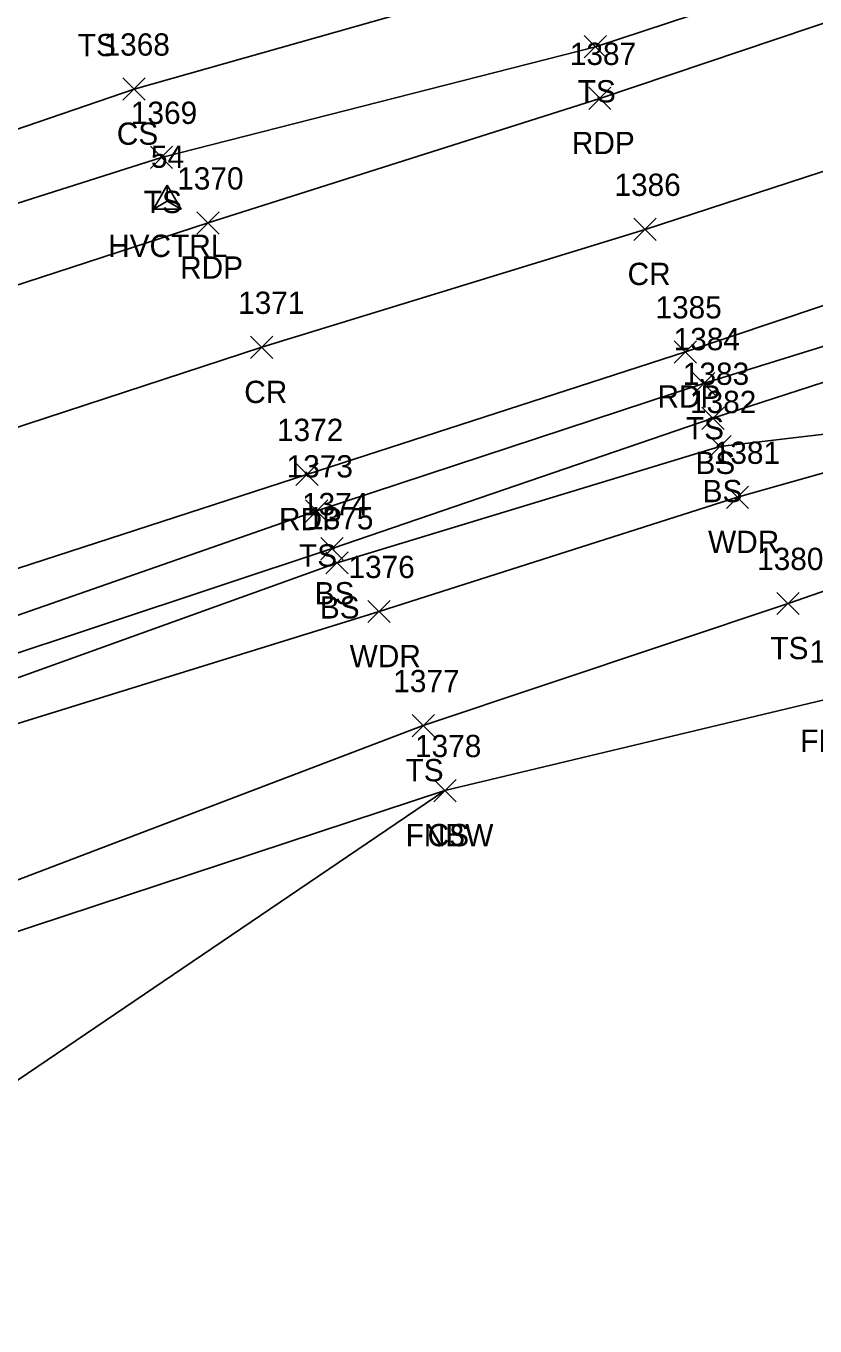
# Model space of a CAD drawing. Extents: x 1443064 to 1445163, y 544063 to 544655.
# Drawn here: x 1443595.4 to 1443666.1, y 544191.5 to 544308.2 of the extents above; entities that cross this region are included whole.
import ezdxf

# ---------------------------------------------------------------- set-up
doc = ezdxf.new("R2010")
doc.units = 0
for name, color, linetype in [('C_A', 7, 'Continuous'), ('C_I', 7, 'Continuous'), ('CPSM', 7, 'Continuous'), ('L_A', 7, 'Continuous'), ('L_I', 7, 'Continuous'), ('L_TIC', 7, 'Continuous'), ('LAWA', 7, 'Continuous'), ('LELB', 7, 'Continuous'), ('LFNC', 7, 'Continuous'), ('P_A', 7, 'Continuous'), ('P_I', 7, 'Continuous'), ('P_TIC', 7, 'Continuous'), ('PET', 7, 'Continuous'), ('PRC', 7, 'Continuous')]:
    doc.layers.add(name, color=color, linetype=linetype)

msp = doc.modelspace()

# ---------------------------------------------------------------- linework, layer by layer
at = {"layer": 'CPSM'}
for p, q in [((1443606.79, 544291.73), (1443608.04, 544293.9)), ((1443609.29, 544291.73), (1443608.04, 544293.9)), ((1443608.04, 544292.45), (1443608.04, 544293.9)), ((1443606.79, 544291.73), (1443608.04, 544292.45)), ((1443608.04, 544292.45), (1443608.04, 544292.45)), ((1443608.04, 544292.45), (1443609.29, 544291.73)), ((1443606.79, 544291.73), (1443609.29, 544291.73))]:
    msp.add_line(p, q, dxfattribs=at)
at = {"layer": 'L_TIC'}
for points in [[(1443645.45, 544305.32), (1443647.45, 544307.32)], [(1443647.45, 544305.32), (1443645.45, 544307.32)], [(1443604.06, 544301.52), (1443606.06, 544303.52)], [(1443606.06, 544301.52), (1443604.06, 544303.52)], [(1443606.52, 544295.39), (1443608.52, 544297.39)], [(1443608.52, 544295.39), (1443606.52, 544297.39)], [(1443655.15, 544275.08), (1443657.15, 544277.08)], [(1443657.15, 544275.08), (1443655.15, 544277.08)], [(1443655.98, 544271.97), (1443657.98, 544273.97)], [(1443657.98, 544271.97), (1443655.98, 544273.97)], [(1443656.62, 544269.44), (1443658.62, 544271.44)], [(1443658.62, 544269.44), (1443656.62, 544271.44)], [(1443658.19, 544264.88), (1443660.19, 544266.88)], [(1443660.19, 544264.88), (1443658.19, 544266.88)], [(1443620.44, 544263.66), (1443622.44, 544265.66)], [(1443622.44, 544263.66), (1443620.44, 544265.66)], [(1443621.82, 544260.27), (1443623.82, 544262.27)], [(1443623.82, 544260.27), (1443621.82, 544262.27)], [(1443622.27, 544259), (1443624.27, 544261)], [(1443624.27, 544259), (1443622.27, 544261)], [(1443662.73, 544255.35), (1443664.73, 544257.35)], [(1443664.73, 544255.35), (1443662.73, 544257.35)], [(1443626.04, 544254.63), (1443628.04, 544256.63)], [(1443628.04, 544254.63), (1443626.04, 544256.63)], [(1443630, 544244.39), (1443632, 544246.39)], [(1443632, 544244.39), (1443630, 544246.39)], [(1443631.95, 544238.56), (1443633.95, 544240.56)], [(1443633.95, 544238.56), (1443631.95, 544240.56)], [(1443631.95, 544238.56), (1443633.95, 544240.56)], [(1443633.95, 544238.56), (1443631.95, 544240.56)]]:
    msp.add_lwpolyline(points, dxfattribs=at)
at = {"layer": 'LAWA'}
msp.add_lwpolyline([(1443500.75, 544181.56), (1443538.36, 544200.41), (1443545.67, 544211.73), (1443545.24, 544222.13), (1443545.25, 544228.26), (1443572.28, 544239.94), (1443578.87, 544240.7), (1443627.04, 544255.63), (1443659.19, 544265.88), (1443688.01, 544274.03), (1443699.53, 544278.63), (1443728.36, 544290.25)], dxfattribs=at)
at = {"layer": 'LELB'}
for points in [[(1443073.59, 544128.34), (1443116.66, 544141.89), (1443162.8, 544149.75), (1443198.07, 544157.24), (1443242.5, 544173.41), (1443262.84, 544182.05), (1443307.11, 544199.46), (1443348.85, 544214.35), (1443394.74, 544233.02), (1443435.02, 544243.93), (1443473.16, 544259.47), (1443514.32, 544272.16), (1443555.56, 544285.54), (1443605.06, 544302.52), (1443644.56, 544313.72), (1443676.09, 544324.26), (1443689.45, 544326.75), (1443708.55, 544330.01), (1443714.07, 544333.45), (1443742.84, 544349.83), (1443793.92, 544368.99), (1443822.61, 544377.56)], [(1443074.67, 544122.4), (1443120.32, 544131.74), (1443165.11, 544143.77), (1443199.58, 544153.13), (1443245.24, 544167.88), (1443264.59, 544177.57), (1443308.86, 544194.48), (1443350.56, 544209.36), (1443397.32, 544225.82), (1443437.1, 544238.98), (1443476.53, 544253.14), (1443516.75, 544265.8), (1443558.95, 544280.95), (1443607.52, 544296.39), (1443646.45, 544306.32), (1443685.12, 544319.06), (1443714.26, 544329.16), (1443721.31, 544331.26), (1443744.28, 544345.57), (1443795.65, 544366.53), (1443822.61, 544377.56)], [(1443082.68, 544086.51), (1443130.13, 544099.67), (1443144.13, 544104.98), (1443172.72, 544113.76), (1443212.83, 544125.42), (1443253.97, 544138.87), (1443319.39, 544160.76), (1443361, 544176.06), (1443409.52, 544193.8), (1443447.54, 544206.03), (1443485.93, 544218.99), (1443527.17, 544233.73), (1443570.65, 544246.93), (1443621.44, 544264.66), (1443656.15, 544276.08), (1443695.78, 544288.38), (1443720.36, 544296.79), (1443749.28, 544306.83), (1443759.63, 544310.57), (1443806.78, 544328.14), (1443835.8, 544338.24)], [(1443319.92, 544153.98), (1443361.38, 544174.3), (1443410.41, 544191.66), (1443447.48, 544203.1), (1443486.62, 544216.08), (1443527.2, 544231.22), (1443571.34, 544244.18), (1443622.82, 544261.27), (1443656.98, 544272.97), (1443695.69, 544285.56), (1443722.38, 544294.2), (1443748.12, 544301.75), (1443761.69, 544309.21), (1443807.82, 544325.32), (1443837.04, 544335.82)], [(1443347.34, 544164.94), (1443362.1, 544171.53), (1443410.79, 544190.32), (1443447.84, 544201.59), (1443487.26, 544214.65), (1443527.73, 544229.42), (1443571.89, 544241.52), (1443623.27, 544260), (1443657.62, 544270.44), (1443688.01, 544274.03), (1443701.05, 544275.03), (1443736.1, 544284.41), (1443746.14, 544291.27)], [(1443551.85, 544201.5), (1443561.2, 544211.49), (1443566.76, 544221.91), (1443582.29, 544226.85), (1443631, 544245.39), (1443663.73, 544256.35), (1443704.83, 544270.63), (1443733.57, 544280.99), (1443742.56, 544273.31)], [(1443326.71, 544136.88), (1443356.07, 544155.13), (1443385.8, 544161.03), (1443414.14, 544171.77), (1443454.43, 544184.84), (1443493.74, 544198.5), (1443535.62, 544210.92), (1443545.67, 544211.73), (1443551.85, 544201.5), (1443566.51, 544204.54), (1443590.28, 544210.64), (1443632.95, 544239.56)]]:
    msp.add_lwpolyline(points, dxfattribs=at)
at = {"layer": 'LFNC'}
msp.add_lwpolyline([(1443239.88, 544119.45), (1443278.62, 544130.94), (1443320.57, 544148.06), (1443338.13, 544157.08), (1443351.22, 544161.82), (1443363.5, 544166.21), (1443412.24, 544182.91), (1443449.91, 544194.79), (1443489.63, 544207.22), (1443534.54, 544218.89), (1443545.24, 544222.13), (1443555.28, 544222.99), (1443566.76, 544221.91), (1443584.49, 544223.6), (1443632.95, 544239.56), (1443668.35, 544248.03), (1443707.08, 544263.81), (1443742.56, 544273.31)], dxfattribs=at)
at = {"layer": 'P_TIC'}
for points in [[(1443645.84, 544300.68), (1443647.84, 544302.68)], [(1443647.84, 544300.68), (1443645.84, 544302.68)], [(1443610.7, 544289.5), (1443612.7, 544291.5)], [(1443612.7, 544289.5), (1443610.7, 544291.5)], [(1443649.9, 544288.93), (1443651.9, 544290.93)], [(1443651.9, 544288.93), (1443649.9, 544290.93)], [(1443615.51, 544278.34), (1443617.51, 544280.34)], [(1443617.51, 544278.34), (1443615.51, 544280.34)], [(1443653.52, 544277.93), (1443655.52, 544279.93)], [(1443655.52, 544277.93), (1443653.52, 544279.93)], [(1443619.57, 544266.93), (1443621.57, 544268.93)], [(1443621.57, 544266.93), (1443619.57, 544268.93)]]:
    msp.add_lwpolyline(points, dxfattribs=at)
at = {"layer": 'PET'}
for points in [[(1443075.39, 544117.71), (1443121.41, 544129.24), (1443165.99, 544140.07), (1443200.71, 544149.88), (1443246.42, 544165.39), (1443265.96, 544172.48), (1443311.2, 544187.88), (1443352.92, 544202.76), (1443399.28, 544220.13), (1443438.78, 544233.67), (1443478.75, 544247.35), (1443518.41, 544260.6), (1443561.23, 544274.05), (1443611.7, 544290.5), (1443646.84, 544301.68), (1443684.98, 544314.55), (1443724.57, 544327.54), (1443735.41, 544331.22), (1443748.81, 544336.36), (1443799.43, 544353.96), (1443827.31, 544364.14)], [(1443081.93, 544089.54), (1443128.67, 544104.01), (1443173.03, 544117.15), (1443209.23, 544128.71), (1443253.49, 544142.88), (1443273.3, 544149.07), (1443318.27, 544165.2), (1443359.78, 544179.84), (1443408.54, 544196.96), (1443445.92, 544210.12), (1443484.92, 544223.61), (1443525.67, 544237.02), (1443568.63, 544251.04), (1443620.57, 544267.93), (1443654.52, 544278.93), (1443694.69, 544292.43), (1443717.24, 544299.44), (1443752.8, 544310.97), (1443757.72, 544314.31), (1443805.74, 544330.07), (1443835.35, 544341.18)]]:
    msp.add_lwpolyline(points, dxfattribs=at)
at = {"layer": 'PRC'}
msp.add_lwpolyline([(1443078.47, 544103.68), (1443125.02, 544115.93), (1443169.41, 544128.22), (1443204.47, 544139.4), (1443250.36, 544154.3), (1443269.99, 544160.83), (1443315.13, 544176.71), (1443356.58, 544191.19), (1443403.59, 544208.05), (1443442.67, 544222.02), (1443482.15, 544235.41), (1443522.16, 544248.37), (1443565.47, 544262.64), (1443616.51, 544279.34), (1443650.9, 544289.93), (1443689.58, 544302.53), (1443728.44, 544315.77), (1443753.53, 544324.68), (1443803.56, 544342.2), (1443830.96, 544352.16)], dxfattribs=at)

# ---------------------------------------------------------------- texts
at = {"layer": 'C_A'}
msp.add_text('HVCTRL', height=2, dxfattribs=at).set_placement((1443602.73, 544287.45))
at = {"layer": 'C_I'}
msp.add_text('54', height=2, dxfattribs=at).set_placement((1443606.57, 544295.45))
at = {"layer": 'L_A'}
for s, p in [('TS', (1443600.01, 544305.47)), ('TS', (1443644.86, 544301.32)), ('CS', (1443603.51, 544297.52)), ('TS', (1443605.93, 544291.39)), ('TS', (1443654.56, 544271.08)), ('BS', (1443655.42, 544267.97)), ('BS', (1443656.06, 544265.44)), ('WDR', (1443656.55, 544260.88)), ('TS', (1443619.85, 544259.66)), ('BS', (1443621.26, 544256.27)), ('BS', (1443621.72, 544255)), ('WDR', (1443624.4, 544250.63)), ('TS', (1443662.14, 544251.35)), ('FNBW', (1443664.82, 544243.03)), ('TS', (1443629.41, 544240.39)), ('FNBW', (1443629.42, 544234.56)), ('CS', (1443631.39, 544234.56))]:
    msp.add_text(s, height=2, dxfattribs=at).set_placement(p)
at = {"layer": 'L_I'}
for s, p in [('1368', (1443602.32, 544305.52)), ('1369', (1443604.77, 544299.39)), ('1384', (1443653.46, 544279.08)), ('1383', (1443654.29, 544275.97)), ('1382', (1443654.93, 544273.44)), ('1381', (1443657.06, 544268.88)), ('1373', (1443618.74, 544267.66)), ('1374', (1443620.12, 544264.27)), ('1375', (1443620.58, 544263)), ('1376', (1443624.29, 544258.63)), ('1380', (1443660.95, 544259.35)), ('1379', (1443665.65, 544251.03)), ('1377', (1443628.31, 544248.39)), ('1378', (1443630.26, 544242.56)), ('1378', (1443630.26, 544242.56))]:
    msp.add_text(s, height=2, dxfattribs=at).set_placement(p)
at = {"layer": 'P_A'}
for s, p in [('RDP', (1443644.33, 544296.68)), ('RDP', (1443609.19, 544285.5)), ('CR', (1443649.33, 544284.93)), ('CR', (1443614.94, 544274.34)), ('RDP', (1443652.01, 544273.93)), ('RDP', (1443618.06, 544262.93))]:
    msp.add_text(s, height=2, dxfattribs=at).set_placement(p)
at = {"layer": 'P_I'}
for s, p in [('1387', (1443644.15, 544304.68)), ('1370', (1443608.93, 544293.5)), ('1386', (1443648.15, 544292.93)), ('1371', (1443614.39, 544282.34)), ('1385', (1443651.83, 544281.93)), ('1372', (1443617.88, 544270.93))]:
    msp.add_text(s, height=2, dxfattribs=at).set_placement(p)

doc.saveas('drawing.dxf')
